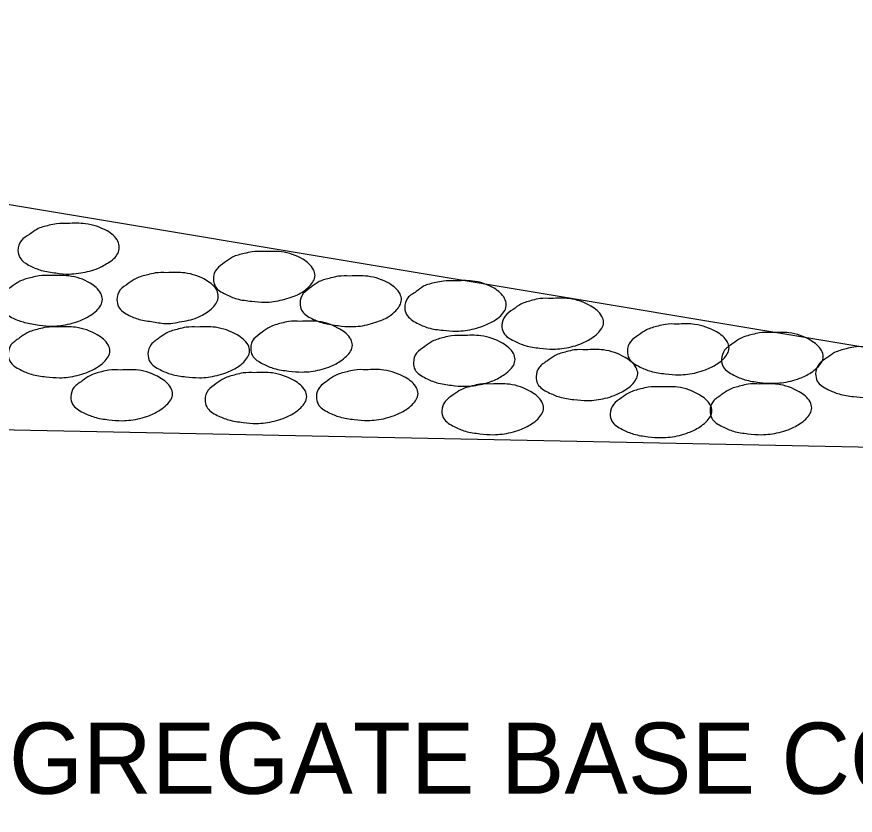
# Model space of a CAD drawing. Extents: x 1929624 to 1935547, y 596315 to 605721.
# Drawn here: x 1933067.9 to 1933138.6, y 604298.8 to 604366.1 of the extents above; entities that cross this region are included whole.
import ezdxf

# ---------------------------------------------------------------- set-up
doc = ezdxf.new("R2010")
doc.units = 0
doc.layers.add('Default', color=7, linetype='Continuous')

msp = doc.modelspace()

# ---------------------------------------------------------------- linework, layer by layer
at = {"layer": 'Default'}
for p, q in [((1932972.315, 604366.131), (1933363.545, 604300.921)), ((1932793.718, 604336.775), (1933196.635, 604328.731))]:
    msp.add_line(p, q, dxfattribs=at)
for points in [[(1933072.215, 604348.711), (1933073.715, 604348.681), (1933075.535, 604348.071), (1933076.455, 604347.201), (1933076.565, 604346.701), (1933076.115, 604345.751), (1933075.585, 604345.361), (1933074.605, 604344.861), (1933073.125, 604344.521), (1933072.355, 604344.441), (1933071.225, 604344.531), (1933069.995, 604344.751), (1933069.055, 604345.131), (1933068.185, 604345.831), (1933068.025, 604346.421), (1933068.295, 604347.251), (1933068.995, 604347.781), (1933069.615, 604348.211), (1933070.645, 604348.551), (1933071.285, 604348.681), (1933072.215, 604348.711)], [(1933088.705, 604346.331), (1933090.215, 604346.311), (1933092.045, 604345.691), (1933092.925, 604344.811), (1933093.065, 604344.321), (1933092.575, 604343.401), (1933092.055, 604342.961), (1933091.055, 604342.491), (1933089.575, 604342.131), (1933088.835, 604342.061), (1933087.725, 604342.151), (1933086.475, 604342.351), (1933085.525, 604342.741), (1933084.635, 604343.441), (1933084.495, 604344.041), (1933084.775, 604344.861), (1933085.445, 604345.411), (1933086.105, 604345.861), (1933087.105, 604346.171), (1933087.755, 604346.311), (1933088.705, 604346.331)], [(1933070.785, 604344.321), (1933072.315, 604344.281), (1933074.105, 604343.681), (1933075.005, 604342.791), (1933075.145, 604342.311), (1933074.665, 604341.371), (1933074.115, 604340.951), (1933073.165, 604340.481), (1933071.655, 604340.111), (1933070.925, 604340.051), (1933069.805, 604340.141), (1933068.585, 604340.371), (1933067.625, 604340.721), (1933066.735, 604341.431), (1933066.575, 604342.041), (1933066.855, 604342.881), (1933067.545, 604343.411), (1933068.195, 604343.831), (1933069.215, 604344.161), (1933069.815, 604344.281), (1933070.785, 604344.321)], [(1933080.555, 604344.551), (1933082.095, 604344.531), (1933083.905, 604343.911), (1933084.795, 604343.051), (1933084.905, 604342.541), (1933084.435, 604341.601), (1933083.925, 604341.201), (1933082.955, 604340.701), (1933081.455, 604340.371), (1933080.715, 604340.261), (1933079.585, 604340.391), (1933078.375, 604340.591), (1933077.405, 604340.951), (1933076.515, 604341.681), (1933076.365, 604342.271), (1933076.645, 604343.101), (1933077.325, 604343.631), (1933077.985, 604344.071), (1933078.965, 604344.381), (1933079.605, 604344.531), (1933080.555, 604344.551)], [(1933095.995, 604344.271), (1933097.505, 604344.251), (1933099.335, 604343.631), (1933100.225, 604342.761), (1933100.345, 604342.271), (1933099.865, 604341.341), (1933099.345, 604340.901), (1933098.365, 604340.441), (1933096.885, 604340.061), (1933096.135, 604340.011), (1933095.015, 604340.091), (1933093.785, 604340.311), (1933092.805, 604340.681), (1933091.935, 604341.391), (1933091.805, 604341.981), (1933092.075, 604342.791), (1933092.755, 604343.351), (1933093.415, 604343.801), (1933094.395, 604344.111), (1933095.035, 604344.251), (1933095.995, 604344.271)], [(1933104.815, 604343.861), (1933106.325, 604343.851), (1933108.155, 604343.241), (1933109.045, 604342.381), (1933109.185, 604341.881), (1933108.715, 604340.921), (1933108.165, 604340.511), (1933107.205, 604340.051), (1933105.735, 604339.691), (1933104.955, 604339.631), (1933103.855, 604339.701), (1933102.605, 604339.911), (1933101.655, 604340.311), (1933100.785, 604341.031), (1933100.625, 604341.601), (1933100.875, 604342.431), (1933101.595, 604342.961), (1933102.215, 604343.411), (1933103.245, 604343.721), (1933103.885, 604343.851), (1933104.815, 604343.861)], [(1933112.985, 604342.381), (1933114.495, 604342.371), (1933116.315, 604341.731), (1933117.235, 604340.871), (1933117.375, 604340.371), (1933116.875, 604339.441), (1933116.345, 604339.021), (1933115.385, 604338.531), (1933113.875, 604338.161), (1933113.135, 604338.111), (1933112.005, 604338.191), (1933110.785, 604338.411), (1933109.835, 604338.801), (1933108.945, 604339.501), (1933108.805, 604340.121), (1933109.075, 604340.901), (1933109.755, 604341.461), (1933110.415, 604341.901), (1933111.395, 604342.231), (1933112.015, 604342.371), (1933112.985, 604342.381)], [(1933091.825, 604340.451), (1933093.335, 604340.441), (1933095.155, 604339.801), (1933096.075, 604338.941), (1933096.215, 604338.441), (1933095.715, 604337.511), (1933095.185, 604337.091), (1933094.225, 604336.601), (1933092.715, 604336.231), (1933091.975, 604336.181), (1933090.845, 604336.261), (1933089.625, 604336.481), (1933088.675, 604336.871), (1933087.785, 604337.571), (1933087.645, 604338.191), (1933087.915, 604338.971), (1933088.595, 604339.531), (1933089.255, 604339.971), (1933090.235, 604340.301), (1933090.855, 604340.441), (1933091.825, 604340.451)], [(1933123.565, 604340.221), (1933125.075, 604340.201), (1933126.895, 604339.561), (1933127.815, 604338.711), (1933127.955, 604338.211), (1933127.465, 604337.271), (1933126.935, 604336.851), (1933125.965, 604336.371), (1933124.455, 604335.991), (1933123.725, 604335.951), (1933122.585, 604336.031), (1933121.365, 604336.241), (1933120.415, 604336.631), (1933119.525, 604337.331), (1933119.385, 604337.961), (1933119.655, 604338.741), (1933120.335, 604339.301), (1933120.995, 604339.731), (1933121.975, 604340.061), (1933122.595, 604340.201), (1933123.565, 604340.221)], [(1933071.375, 604339.971), (1933072.885, 604339.951), (1933074.715, 604339.311), (1933075.635, 604338.461), (1933075.775, 604337.961), (1933075.275, 604337.021), (1933074.745, 604336.601), (1933073.775, 604336.121), (1933072.265, 604335.751), (1933071.535, 604335.701), (1933070.395, 604335.781), (1933069.175, 604335.991), (1933068.225, 604336.381), (1933067.345, 604337.091), (1933067.205, 604337.711), (1933067.465, 604338.491), (1933068.155, 604339.051), (1933068.805, 604339.481), (1933069.785, 604339.811), (1933070.415, 604339.951), (1933071.375, 604339.971)], [(1933083.155, 604339.971), (1933084.665, 604339.951), (1933086.495, 604339.311), (1933087.415, 604338.461), (1933087.555, 604337.961), (1933087.055, 604337.021), (1933086.525, 604336.601), (1933085.555, 604336.121), (1933084.045, 604335.751), (1933083.315, 604335.701), (1933082.175, 604335.781), (1933080.965, 604335.991), (1933080.015, 604336.381), (1933079.125, 604337.091), (1933078.985, 604337.711), (1933079.245, 604338.491), (1933079.935, 604339.051), (1933080.585, 604339.481), (1933081.565, 604339.811), (1933082.195, 604339.951), (1933083.155, 604339.971)], [(1933131.495, 604339.501), (1933133.005, 604339.481), (1933134.835, 604338.851), (1933135.755, 604337.991), (1933135.895, 604337.491), (1933135.395, 604336.561), (1933134.865, 604336.131), (1933133.895, 604335.651), (1933132.385, 604335.281), (1933131.655, 604335.231), (1933130.515, 604335.311), (1933129.295, 604335.531), (1933128.345, 604335.921), (1933127.465, 604336.621), (1933127.325, 604337.241), (1933127.585, 604338.021), (1933128.275, 604338.581), (1933128.925, 604339.021), (1933129.905, 604339.341), (1933130.535, 604339.481), (1933131.495, 604339.501)], [(1933105.535, 604339.251), (1933107.045, 604339.241), (1933108.865, 604338.601), (1933109.785, 604337.741), (1933109.925, 604337.241), (1933109.435, 604336.311), (1933108.905, 604335.891), (1933107.935, 604335.401), (1933106.425, 604335.031), (1933105.695, 604334.981), (1933104.555, 604335.061), (1933103.335, 604335.281), (1933102.385, 604335.671), (1933101.495, 604336.371), (1933101.355, 604336.991), (1933101.625, 604337.771), (1933102.305, 604338.331), (1933102.965, 604338.771), (1933103.945, 604339.101), (1933104.565, 604339.241), (1933105.535, 604339.251)], [(1933115.865, 604338.051), (1933117.375, 604338.041), (1933119.205, 604337.401), (1933120.125, 604336.541), (1933120.265, 604336.041), (1933119.765, 604335.111), (1933119.235, 604334.691), (1933118.265, 604334.201), (1933116.755, 604333.831), (1933116.025, 604333.781), (1933114.885, 604333.861), (1933113.665, 604334.081), (1933112.715, 604334.471), (1933111.835, 604335.171), (1933111.695, 604335.791), (1933111.955, 604336.571), (1933112.645, 604337.131), (1933113.295, 604337.571), (1933114.275, 604337.901), (1933114.905, 604338.041), (1933115.865, 604338.051)], [(1933139.425, 604338.301), (1933140.935, 604338.291), (1933142.765, 604337.651), (1933143.685, 604336.791), (1933143.825, 604336.291), (1933143.325, 604335.361), (1933142.795, 604334.931), (1933141.825, 604334.451), (1933140.315, 604334.081), (1933139.585, 604334.031), (1933138.445, 604334.111), (1933137.235, 604334.331), (1933136.285, 604334.721), (1933135.395, 604335.421), (1933135.255, 604336.041), (1933135.515, 604336.821), (1933136.205, 604337.381), (1933136.855, 604337.821), (1933137.835, 604338.141), (1933138.465, 604338.291), (1933139.425, 604338.301)], [(1933076.655, 604336.351), (1933078.175, 604336.341), (1933079.995, 604335.701), (1933080.915, 604334.841), (1933081.055, 604334.341), (1933080.555, 604333.411), (1933080.025, 604332.991), (1933079.055, 604332.501), (1933077.545, 604332.131), (1933076.815, 604332.081), (1933075.675, 604332.161), (1933074.465, 604332.381), (1933073.515, 604332.771), (1933072.625, 604333.471), (1933072.485, 604334.091), (1933072.745, 604334.871), (1933073.435, 604335.431), (1933074.085, 604335.871), (1933075.075, 604336.201), (1933075.695, 604336.341), (1933076.655, 604336.351)], [(1933087.975, 604336.121), (1933089.485, 604336.101), (1933091.305, 604335.461), (1933092.225, 604334.611), (1933092.365, 604334.111), (1933091.865, 604333.171), (1933091.335, 604332.751), (1933090.375, 604332.271), (1933088.865, 604331.901), (1933088.125, 604331.851), (1933086.995, 604331.931), (1933085.775, 604332.151), (1933084.825, 604332.531), (1933083.935, 604333.241), (1933083.795, 604333.861), (1933084.065, 604334.641), (1933084.745, 604335.201), (1933085.405, 604335.641), (1933086.385, 604335.961), (1933087.005, 604336.101), (1933087.975, 604336.121)], [(1933097.355, 604336.371), (1933098.865, 604336.351), (1933100.685, 604335.711), (1933101.605, 604334.861), (1933101.745, 604334.361), (1933101.245, 604333.421), (1933100.715, 604333.001), (1933099.755, 604332.521), (1933098.245, 604332.151), (1933097.505, 604332.101), (1933096.375, 604332.181), (1933095.155, 604332.391), (1933094.205, 604332.781), (1933093.315, 604333.491), (1933093.175, 604334.111), (1933093.445, 604334.891), (1933094.125, 604335.451), (1933094.785, 604335.891), (1933095.765, 604336.211), (1933096.385, 604336.351), (1933097.355, 604336.371)], [(1933107.935, 604335.171), (1933109.445, 604335.151), (1933111.265, 604334.511), (1933112.185, 604333.661), (1933112.325, 604333.161), (1933111.835, 604332.221), (1933111.305, 604331.801), (1933110.335, 604331.321), (1933108.825, 604330.951), (1933108.095, 604330.901), (1933106.955, 604330.981), (1933105.735, 604331.191), (1933104.785, 604331.581), (1933103.895, 604332.291), (1933103.755, 604332.911), (1933104.025, 604333.691), (1933104.705, 604334.251), (1933105.365, 604334.691), (1933106.345, 604335.011), (1933106.965, 604335.151), (1933107.935, 604335.171)], [(1933130.535, 604335.171), (1933132.045, 604335.151), (1933133.865, 604334.511), (1933134.785, 604333.661), (1933134.925, 604333.161), (1933134.425, 604332.221), (1933133.895, 604331.801), (1933132.935, 604331.321), (1933131.415, 604330.951), (1933130.685, 604330.901), (1933129.545, 604330.981), (1933128.335, 604331.191), (1933127.385, 604331.581), (1933126.495, 604332.291), (1933126.355, 604332.911), (1933126.615, 604333.691), (1933127.305, 604334.251), (1933127.955, 604334.691), (1933128.945, 604335.011), (1933129.565, 604335.151), (1933130.535, 604335.171)], [(1933122.115, 604334.921), (1933123.625, 604334.901), (1933125.455, 604334.261), (1933126.365, 604333.411), (1933126.505, 604332.911), (1933126.015, 604331.971), (1933125.485, 604331.551), (1933124.515, 604331.071), (1933123.005, 604330.701), (1933122.275, 604330.651), (1933121.135, 604330.731), (1933119.915, 604330.951), (1933118.965, 604331.341), (1933118.075, 604332.041), (1933117.935, 604332.661), (1933118.205, 604333.441), (1933118.885, 604334.001), (1933119.545, 604334.441), (1933120.525, 604334.761), (1933121.145, 604334.901), (1933122.115, 604334.921)]]:
    msp.add_spline(points, degree=3, dxfattribs=at)

# ---------------------------------------------------------------- texts
msp.add_text('AGGREGATE BASE COURSE (CLASS 7)', height=6, dxfattribs=at).set_placement((1933055.678, 604300.624))

doc.saveas('drawing.dxf')
